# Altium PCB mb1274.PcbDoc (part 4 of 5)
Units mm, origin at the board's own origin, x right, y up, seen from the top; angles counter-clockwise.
Board outline 70 x 105 mm, 4 copper layers (Top Layer, Mid-Layer 1, Mid-Layer 2, Bottom Layer), stack 1.58 mm thick; 329 components, 271 nets, 1213 pads, 779 vias.
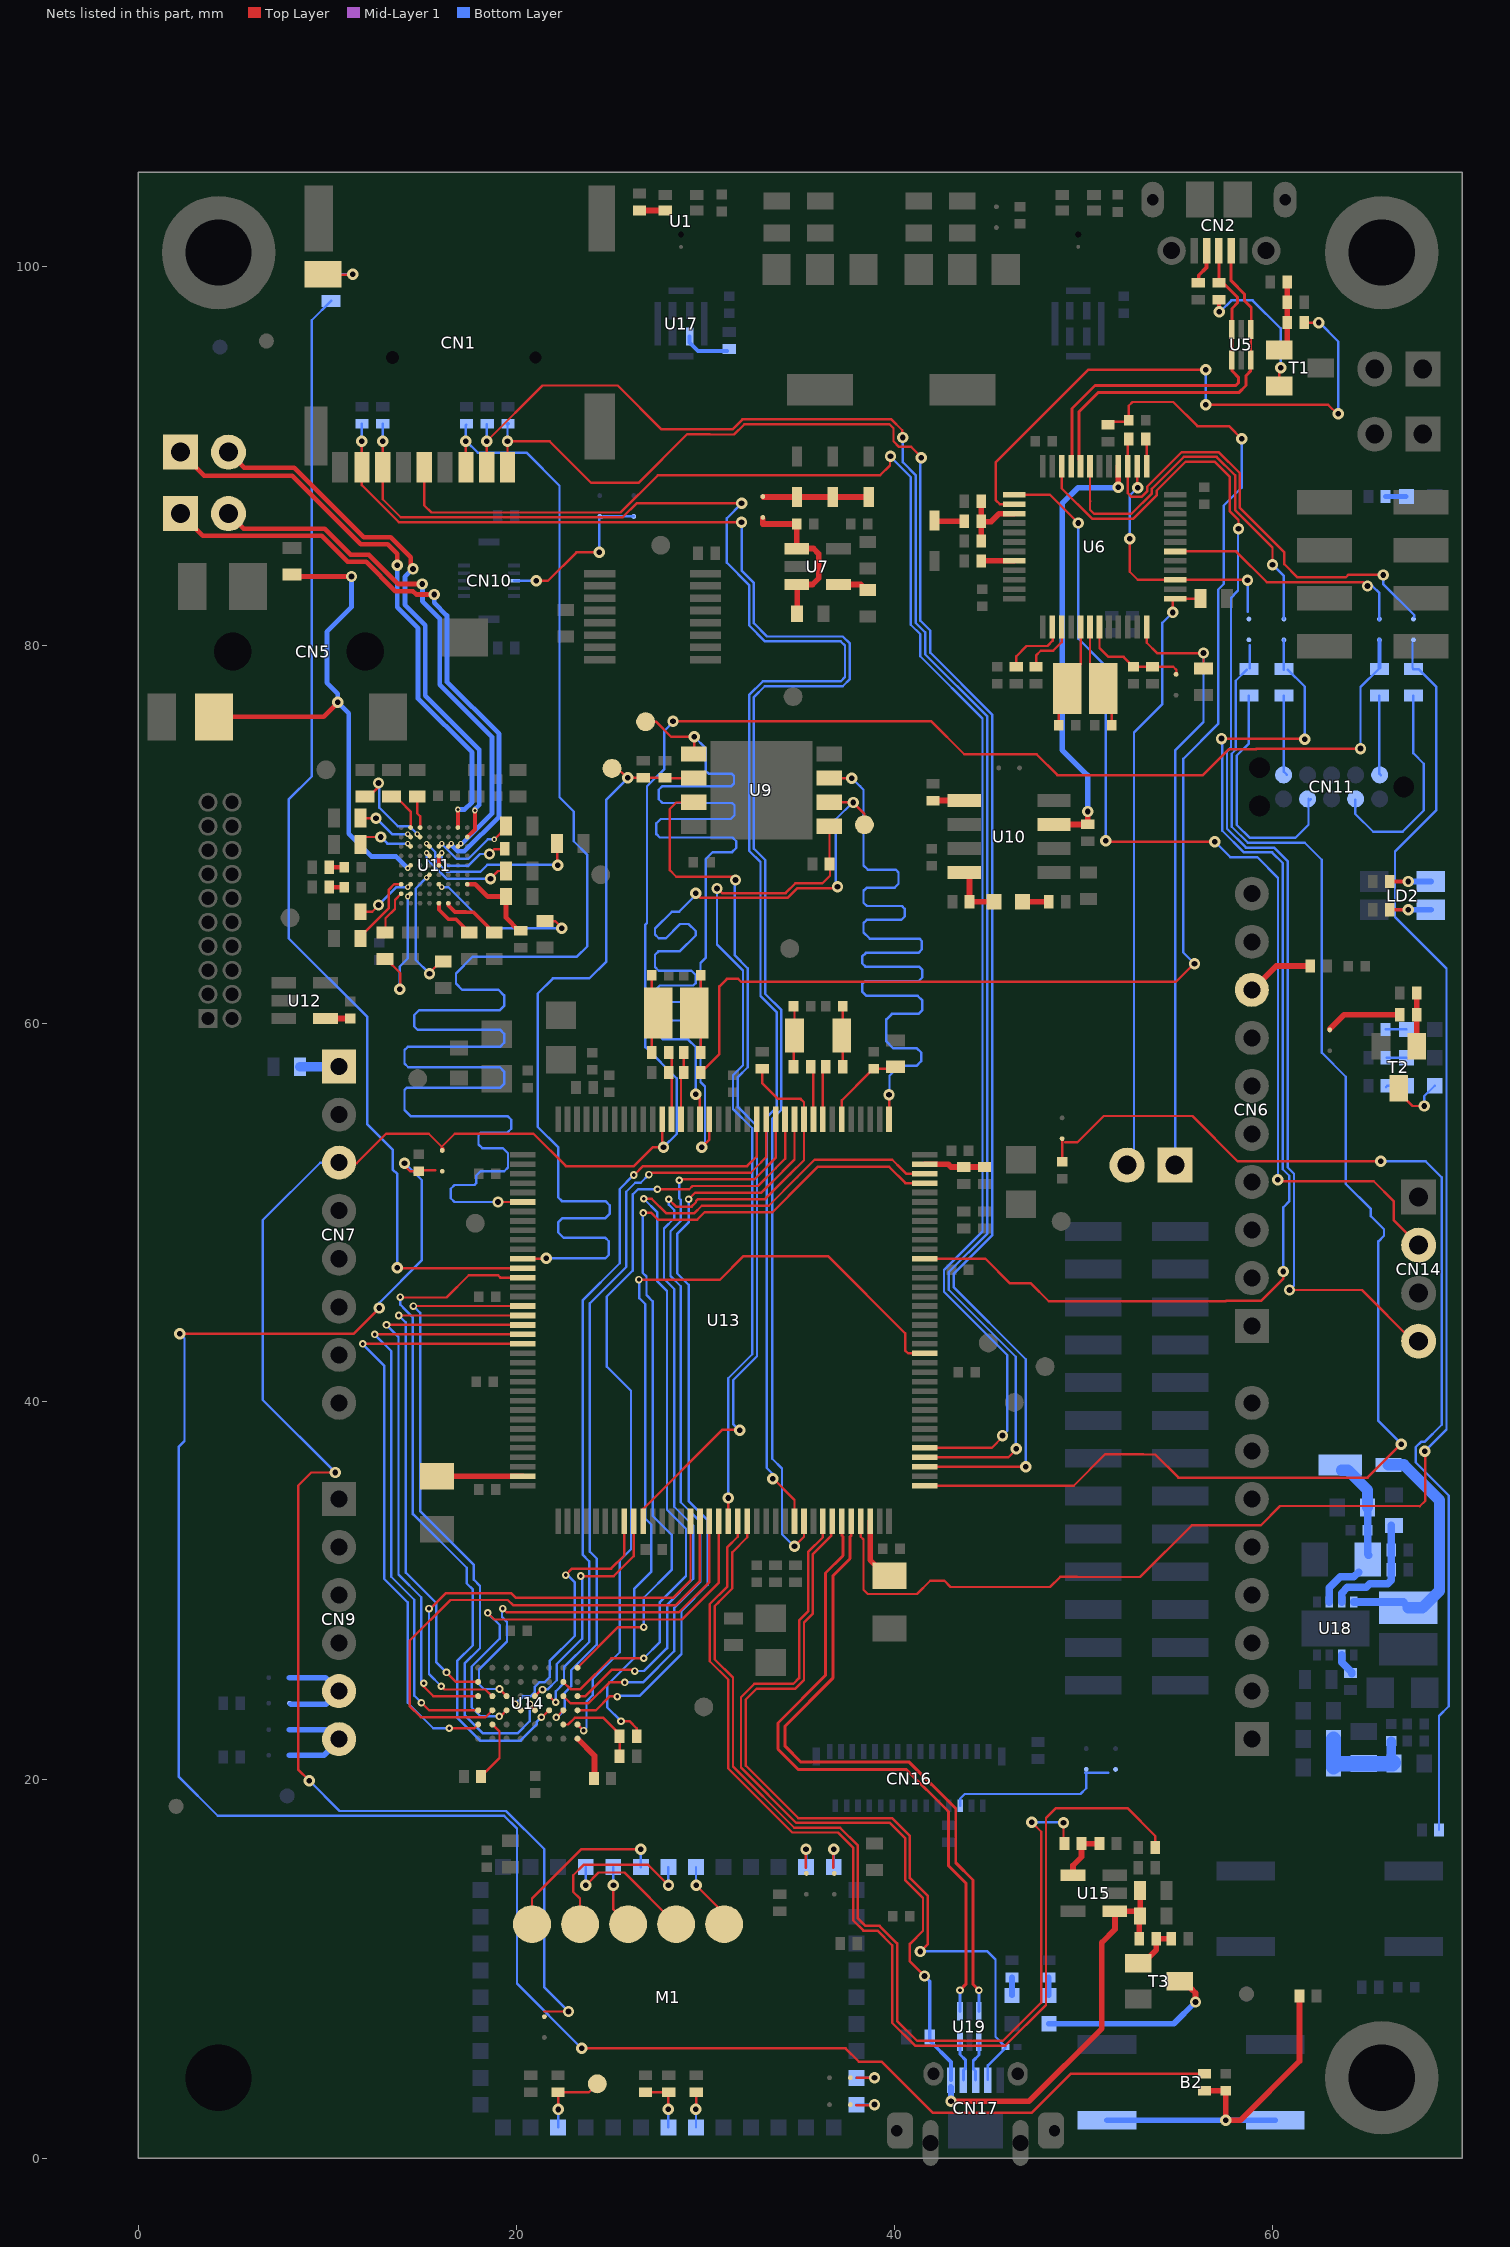
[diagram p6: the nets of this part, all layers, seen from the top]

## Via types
v1: diameter 0.6, hole 0.3, Top Layer to Bottom Layer, tented both sides, 574 vias
v2: diameter 0.4, hole 0.2, Top Layer to Bottom Layer, tented both sides, 125 vias
v3: diameter 0.8, hole 0.4, Top Layer to Bottom Layer, tented both sides, 49 vias
v4: diameter 0.3, hole 0.15, Top Layer to Bottom Layer, tented both sides, 31 vias

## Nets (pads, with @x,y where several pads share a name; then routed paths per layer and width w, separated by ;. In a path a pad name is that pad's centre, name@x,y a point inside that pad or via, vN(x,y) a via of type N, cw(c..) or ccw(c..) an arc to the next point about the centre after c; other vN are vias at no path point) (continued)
NetB2_1: B2.1 B2.2 C78.2 R72.1 R73.2 | length 20.2
  Top Layer w0.3: R73.2@56.375,3.55 C78.2@57.5,3.55 v1(57.5,2) 58.275,2 61.4,5.125 R72.1@61.4,8.575
  Bottom Layer w0.3: B2.1@51.225,2 v1(57.5,2) B2.2@60.125,2
NetC11_2: C11.2 C17.2 SB2.2 U7.1 U7.3 | length 8.7
  Top Layer w0.3: SB2.2@33.025,86.675 33.025,86.4 C11.2@34.825,86.4 U7.1@34.825,85.1 ; C17.2@34.825,81.65 34.85,81.675 U7.3@34.85,83.2 ; U7.3@34.825,83.2 U7.3@34.85,83.2 ; U7.1@34.875,85.1 35.7,85.1 35.975,84.825 35.975,83.525 35.65,83.2 U7.3@34.85,83.2
NetC14_2: C14.2 U7.4 | length 1.5
  Top Layer w0.3: U7.4@37.025,83.2 38.2,83.2 C14.2@38.425,82.975
NetC22_2: C22.2 U11.F1 | length 1.7
  Top Layer w0.127: C22.2@14.75,72 14.75,71.1 14.903,70.947 U11.F1@14.903,70.328
NetC29_1: C29.1 R32.2 | length 0.8
  Top Layer w0.25: R32.2@10.125,68.25 C29.1@10.9,68.25
NetC31_1: C31.1 R35.2 | length 0.8
  Top Layer w0.25: R35.2@10.1,67.2 C31.1@10.9,67.2
NetC32_2: C32.2 R39.1 U11.A7 | length 4.5
  Top Layer w0.25: U11.A7@17.4,67.35 17.825,67.35 18.475,66.7 C32.2@19.45,66.7 19.45,65.575 20.125,64.9 R39.1@20.225,64.9
NetC33_1: C33.1 U11.G7 | length 3.3
  Top Layer w0.127: C33.1@11.75,65.9 12.375,65.9 12.701,66.226 v1(12.701,66.253) ; v4(14.25,67.2) U11.G7@14.4,67.35
  Bottom Layer w0.127: v1(12.701,66.253) 13.647,67.2 v4(14.25,67.2)
NetC34_2: C34.2 U11.D7 | length 8.6
  Top Layer w0.127: U11.D7@15.9,67.35 v4(16.05,67.2) v4@16.075,67.2 ; C34.2@21.4,65.4 C34.2@21.45,65.35 ; C34.2@21.5,65.4 22.05,65.4 v1@22.4,65.05
  Bottom Layer w0.127: v4@16.075,67.2 16.39,67.2 18.565,65.025 v1(22.4,65.025)
NetC36_1: C36.1 U11.H8 | length 2.4
  Top Layer w0.127: C36.1@13.075,64.8 13.075,65.55 13.575,66.05 13.575,66.525 U11.H8@13.9,66.85
NetC36_2: C36.2 U11.G8 | length 7.2
  Top Layer w0.127: C36.2@13.05,63.4 13.1,63.4 13.85,62.65 v1@13.85,61.8 ; v4(14.25,66.7) U11.G8@14.4,66.85
  Bottom Layer w0.127: v1@13.825,61.85 13.825,63 14.25,63.425 v4(14.25,66.7) ; v1@13.85,61.8 v1@13.85,61.85
  other v1: 13.825,61.8
NetC38_2: C38.2 U11.D9 | length 2.4
  Top Layer w0.2: U11.D9@15.9,66.35 15.9,66 16.4,65.5 16.8,65.5 C38.2@17.5,64.8
NetC39_2: C39.2 U11.C9 | length 3.1
  Top Layer w0.2: U11.C9@16.4,66.35 16.4,66.225 16.748,65.877 17.3,65.877 ; 17.3,65.875 17.725,65.875 C39.2@18.8,64.8
NetC40_1: C40.1 U11.H7 | length 3.8
  Top Layer w0.127: C40.1@11.825,64.675 13.25,66.1 13.25,67.075 13.525,67.35 U11.H7@13.9,67.35
NetC41_2: C41.2 U11.E6 | length 6.8
  Top Layer w0.127: v4(15.25,67.7) U11.E6@15.4,67.85 ; v1(15.401,62.628) 15.401,62.676 16,63.275 C41.2@16.125,63.275
  Bottom Layer w0.127: v4(15.25,67.7) 14.675,67.125 14.675,63.354 v1(15.401,62.628)
NetC43_1: C43.1 R44.2 X2.2 | length 4.1
  Top Layer w0.127: X2.2@27,60.7 27.15,60.85 C43.1@27.15,62.55 ; R44.2@27.15,58.45 27.15,60.175 X2.2@27.5,60.525
NetC44_1: C44.1 R45.2 X2.1 | length 3.9
  Top Layer w0.127: X2.1@29.7,60.2 29.75,60.15 R45.2@29.75,58.45 ; X2.1@29.75,60.375 C44.1@29.75,62.55
NetC45_2: C45.2 U12.4 | length 1.4
  Top Layer w0.3: U12.4@9.825,60.275 9.85,60.25 U12.4@9.9,60.25 C45.2@11.2,60.25
NetC46_1: C46.1 R47.2 X3.2 | length 3
  Top Layer w0.127: R47.2@34.65,57.7 34.65,59.075 X3.2@34.675,59.1 ; C46.1@34.675,60.9 34.7,60.875 X3.2@34.7,59.35
NetC47_1: C47.1 R48.2 X3.1 | length 3.2
  Top Layer w0.127: R48.2@37.25,57.7 X3.1@37.25,59.175 ; C47.1@37.25,60.9 37.25,59.25 X3.1@37.275,59.225
NetC50_2: C50.2 R43.1 U13.6 | length 4.4
  Top Layer w0.127: U13.6@37.2,54.925 37.2,55.925 C50.2@38.7,57.425 ; C50.2@38.9,57.6 39.95,57.6 R43.1@40.1,57.75
NetC57_2: C57.2 R73.1 SB7.2 | length 113.1
  Top Layer w0.127: v1(2.2,43.577) 2.202,43.575 11.375,43.575 v1(12.75,44.95) ; v1@14.075,52.625 v1(14.075,52.6) 14.075,52.475 14.375,52.175 C57.2@14.825,52.175 ; C57.2@14.85,52.225 15.7,52.225 ; v1(23.45,5.8) 37.4,5.8 38.1,5.1 39.3,5.1 42,2.4 47.25,2.4 49.3,4.45 R73.1@56.375,4.45
  Bottom Layer w0.127: v1(2.2,43.577) 2.446,43.331 2.446,37.921 2.15,37.625 2.15,20.15 4.204,18.096 19.345,18.096 20.025,17.416 20.025,9.225 v1(23.45,5.8) ; v1(12.75,44.95) 12.75,45.225 15,47.475 15,51.7 v1@14.088,52.613 ; v1@13.85,52.6 v1(14.075,52.6)
NetC58_2: C58.2 R106.1 SB6.2 | length 59.1
  Top Layer w0.127: C58.2@48.85,52.675 SB6.2@48.85,53.85 ; 49,53.7 49.65,53.7 51.05,55.1 55.741,55.1 58.14,52.701 v1(65.7,52.7)
  Bottom Layer w0.127: v1(65.7,52.7) 68.075,52.7 68.921,51.854 68.921,38.771 68.017,37.867 67.825,37.867 67.538,37.58 67.538,36.787 69.29,35.034 69.29,23.89 68.775,23.375 R106.1@68.775,17.35
NetC64_2: C64.2 U13.71 | length 4.6
  Top Layer w0.3: C64.2@15.775,36.05 U13.71@20.325,36.05
NetC69_2: C69.2 U13.106 | length 2.8
  Top Layer w0.3: U13.106@38.7,33.675 38.7,31.625 C69.2@39.225,31.1
NetC83_2: C83.2 C84.2 D5.2 L3.1 U18.6 | length 7.9
  Bottom Layer w0.4: U18.6@62.975,29.4 62.975,30.15 63.55,30.725 64.275,30.725 C84.2@64.525,30.975 ; L3.1@65,34.4 65,33 65,31.925 C84.2@65.05,31.875
  Bottom Layer w0.6: D5.2@63.625,36.375 63.95,36.375 65,35.325 L3.1@65,34.4
NetC87_2: C87.2 C88.2 L6.2 L7.1 L8.2 | length 5.9
  Bottom Layer w0.5: C87.2@66.25,22.05 66.25,20.975 L7.1@66.325,20.9
  Bottom Layer w0.8: L8.2@63.2,20.675 L6.2@63.2,22.15 ; L8.2@63.225,20.7 63.375,20.85 C88.2@64.8,20.85 66.325,20.85 L7.1@66.375,20.9
NetCN1_10: CN1.10 R79.2 | length 2.5
  Top Layer w0.127: CN1.10@10.025,99.575 11.325,99.575 v1(11.35,99.6)
  Bottom Layer w0.127: R79.2@10.2,99.6 v1(11.35,99.6)
NetCN3_1: CN3.1 U11.B1 | length 30.3
  Top Layer w0.127: U11.B1@16.9,70.35 U11.B1@16.9,70.383
  Top Layer w0.2: U11.B1@16.9,70.383 v4(16.9,71.3)
  Top Layer w0.25: CN3.1@2.23,90.2 3.48,88.95 8.142,88.95 11.769,85.323 13.194,85.323 13.7,84.817 v1(13.7,84.225)
  Bottom Layer w0.25: v1(13.7,84.225) 13.7,81.992 14.798,80.894 14.798,77.169 17.648,74.319 17.648,71.698 17.25,71.3 v4(16.9,71.3)
NetCN3_2: CN3.2 U11.A2 | length 28.8
  Top Layer w0.2: U11.A2@17.4,69.85 17.8,70.25 v4(17.8,71.25)
  Top Layer w0.25: CN3.2@4.77,90.2 5.595,89.375 8.25,89.375 11.925,85.7 13.35,85.7 14.404,84.646 14.404,84.146 v1(14.525,84.025)
  Bottom Layer w0.25: v1(14.525,84.025) 14.1,83.6 14.1,82.125 15.175,81.05 15.175,77.325 18.025,74.475 18.025,71.542 17.8,71.317 v4(17.8,71.25)
NetCN4_1: CN4.1 U11.C3 | length 32.1
  Top Layer w0.2: U11.C3@16.4,69.35 v4(16.55,69.5)
  Top Layer w0.25: CN4.1@2.23,86.95 3.407,85.773 9.694,85.773 11.069,84.398 12.044,84.398 13.594,82.848 14.525,82.848 14.7,82.673 15.254,82.673 15.256,82.675 v1(15.65,82.675)
  Bottom Layer w0.25: v1(15.65,82.675) 15.65,82.233 16.325,81.558 16.325,78.05 19.077,75.298 19.077,70.925 17.25,69.098 16.883,69.098 16.55,69.431 v4(16.55,69.5)
NetCN4_2: CN4.2 U11.B3 | length 28
  Top Layer w0.2: U11.B3@16.9,69.35 v4(17.05,69.5)
  Top Layer w0.25: CN4.2@4.77,86.95 5.57,86.15 9.85,86.15 11.225,84.775 12.2,84.775 13.75,83.225 v1(15.025,83.225)
  Bottom Layer w0.25: v1(15.025,83.225) 15.025,82.325 15.948,81.402 15.948,77.894 18.7,75.142 18.7,71.081 17.119,69.5 v4(17.05,69.5)
NetCN5_3: CN5.3 R12.1 U11.G5 | length 28.6
  Top Layer w0.25: CN5.3@4,76.2 4,76.202 9.802,76.202 10.575,76.975 v1(10.55,76.975) ; R12.1@8.15,83.7 8.225,83.625 v1(11.275,83.625)
  Bottom Layer w0.25: v1(11.275,83.625) 11.275,82 9.975,80.7 9.975,78 10.55,77.425 v1(10.55,76.975) 11.125,76.4 11.125,70.025 12.325,68.825 13.625,68.825 v4(14.25,68.2)
NetCN6_8: CN6.8 R40.1 | length 3.6
  Top Layer w0.3: CN6.8@58.925,61.775 60.175,63.025 R40.1@61.975,63.025
NetCN7_1: CN7.1 R95.2 | length 2.1
  Bottom Layer w0.2: CN7.1@10.65,57.7 CN7.1@10.675,57.675
  Bottom Layer w0.5: R95.2@8.55,57.7 CN7.1@10.65,57.7
NetCN9_5: CN9.5 SB19.2 SB20.2 | length 5.7
  Bottom Layer w0.3: SB19.2@8,25.4 9.9,25.4 CN9.5@10.55,24.75 ; SB20.2@8.075,24 9.93,24 CN9.5@10.62,24.69
NetCN9_6: CN9.6 SB21.2 SB24.2 | length 5.8
  Bottom Layer w0.3: SB24.2@8,21.3 9.825,21.3 CN9.6@10.637,22.113 ; SB21.2@8,22.65 10.1,22.65 CN9.6@10.6,22.15
NetCN10_8: CN10.8 SB13.2 SB14.2 | length 8.7
  Top Layer w0.127: v1(21.05,83.4) 21.666,83.4 23.166,84.9 v1(24.375,84.9)
  Bottom Layer w0.127: CN10.8@19.875,83.4 v1(21.05,83.4) ; v1(24.375,84.9) 24.375,86.75 SB14.2@24.4,86.775 ; SB14.2@24.5,86.725 24.575,86.8 SB13.2@26.2,86.8
NetCN16_24: CN16.24 SB22.2 SB23.2 | length 9.3
  Bottom Layer w0.127: CN16.24@43.46,18.625 43.46,19.01 43.7,19.25 49.825,19.25 50.125,19.55 50.125,20.325 50.15,20.35 ; 50.075,20.375 51.3,20.375
NetD1_2: D1.2 D2.2 D3.2 SB2.1 | length 5.5
  Top Layer w0.3: SB2.1@33.05,87.825 33.055,87.83 D1.2@34.825,87.83 ; D1.2@34.925,87.8 34.955,87.83 D2.2@36.725,87.83 ; D2.2@36.75,87.825 38.62,87.825 D3.2@38.625,87.83
NetD4_2: D4.2 R10.2 | length 1.6
  Top Layer w0.3: D4.2@42.05,86.525 42.075,86.55 R10.2@43.675,86.55
NetD5_1: D5.1 L4.2 U18.8 | length 13.3
  Bottom Layer w0.4: U18.8@64.275,29.4 66.9,29.4 L4.2@67.175,29.125
  Bottom Layer w0.6: D5.1@66.1,36.65 D5.1@66.115,36.65 66.928,36.65 68.8,34.778 68.8,30 67.9,29.1 L4.2@67.15,29.1
NetL2_2: L2.2 R98.2 R99.1 U18.7 | length 6.3
  Bottom Layer w0.4: U18.7@63.625,29.4 63.625,29.875 63.925,30.175 64.925,30.175 65.125,30.375 66.075,30.375 66.25,30.55 R99.1@66.25,31.15 ; R99.1@66.25,31.1 R98.2@66.25,32.125 ; R98.2@66.25,32.15 L2.2@66.25,33.45
NetLD1_1: LD1.1 R37.1 | length 1.4
  Top Layer w0.3: LD1.1@46.75,66.425 R37.1@48.15,66.425 R37.1@48.175,66.425
NetLD1_2: LD1.2 R36.1 U10.8 | length 2.8
  Top Layer w0.3: U10.8@43.85,67.875 43.95,67.775 R36.1@43.95,66.425 ; R36.1@43.95,66.4 43.975,66.425 LD1.2@45.25,66.425
NetLD2_2: LD2.2 R38.1 | length 2.2
  Top Layer w0.2: R38.1@66.175,66 v1(67.15,66)
  Bottom Layer w0.3: v1(67.15,66) LD2.2@68.35,66
NetLD2_3: LD2.3 R34.1 | length 2.2
  Top Layer w0.2: R34.1@66.175,67.5 v1(67.15,67.5)
  Bottom Layer w0.3: v1(67.15,67.5) LD2.3@68.35,67.5
NetLD3_1: LD3.1 R93.2 | length 1.1
  Bottom Layer w0.127: R93.2@65.95,59.675 LD3.1@67.05,59.675
NetLD4_1: LD4.1 R94.1 | length 1
  Bottom Layer w0.127: R94.1@66.025,58.175 LD4.1@67.05,58.175
NetLD5_1: LD5.1 R96.1 | length 1.1
  Bottom Layer w0.127: R96.1@65.975,56.625 66.05,56.7 LD5.1@67.05,56.7
NetLD5_2: LD5.2 T2.3 | length 3.2
  Top Layer w0.127: T2.3@66.65,56.575 66.65,56.35 67.375,55.625 v1(68,55.625)
  Bottom Layer w0.127: v1(68,55.625) 68,56.15 LD5.2@68.55,56.7
NetLD6_1: LD6.1 R97.2 | length 1.1
  Bottom Layer w0.25: R97.2@65.95,87.85 LD6.1@67.05,87.85
NetLD7_1: LD7.1 R107.1 | length 1
  Bottom Layer w0.3: LD7.1@48.15,8.6 R107.1@48.15,9.55
NetLD7_2: LD7.2 T3.3 | length 9.1
  Top Layer w0.3: T3.3@55.65,8.975 55.9,8.725 v1(55.9,8.25)
  Bottom Layer w0.3: LD7.2@48.15,7.1 54.75,7.1 v1(55.9,8.25)
NetLD8_1: LD8.1 R108.2 | length 0.9
  Bottom Layer w0.3: LD8.1@46.2,8.6 R108.2@46.2,9.55
NetM1_4: M1.4 TP20.1 | length 7.1
  Top Layer w0.127: v1(23.668,14.425) 24.343,15.1 25.705,15.1 TP20.1@28.44,12.365
  Bottom Layer w0.127: M1.4@23.661,15.38 23.661,14.432 v1(23.668,14.425)
NetM1_5: M1.5 TP19.1 | length 3.3
  Top Layer w0.127: v1(25.125,14.425) 25.125,13.14 TP19.1@25.9,12.365
  Bottom Layer w0.127: M1.5@25.118,15.38 25.118,14.432 v1(25.125,14.425)
NetM1_6: M1.6 TP17.1 | length 9.1
  Top Layer w0.127: TP17.1@20.82,12.365 20.82,13.72 23.435,16.335 v1(26.568,16.335)
  Bottom Layer w0.127: v1(26.568,16.335) 26.575,16.328 M1.6@26.575,15.38
NetM1_7: M1.7 TP18.1 | length 9.4
  Top Layer w0.127: TP18.1@23.36,12.365 23.36,13.715 23,14.075 23,14.95 23.55,15.5 26.964,15.5 v1(28.039,14.425)
  Bottom Layer w0.127: M1.7@28.032,15.38 28.032,14.432 v1(28.039,14.425)
NetM1_8: M1.8 TP21.1 | length 3.6
  Top Layer w0.127: v1(29.496,14.425) 30.98,12.941 TP21.1@30.98,12.365
  Bottom Layer w0.127: M1.8@29.489,15.38 29.489,14.432 v1(29.496,14.425)
NetM1_12: M1.12 SB8.2 | length 1.9
  Top Layer w0.127: 35.3,15.35 35.3,16.325 v1(35.31,16.335)
  Bottom Layer w0.127: v1(35.31,16.335) 35.317,16.328 M1.12@35.317,15.38
NetM1_13: M1.13 SB9.2 | length 1.9
  Top Layer w0.127: 36.75,15.35 36.75,16.318 v1(36.767,16.335)
  Bottom Layer w0.127: v1(36.767,16.335) 36.774,16.328 M1.13@36.774,15.38
NetM1_21: M1.21 SB11.2 | length 1.9
  Top Layer w0.127: 38,4.25 38.926,4.25 v1(38.929,4.247)
  Bottom Layer w0.127: M1.21@37.974,4.24 38.922,4.24 v1(38.929,4.247)
NetM1_22: M1.22 SB12.2 | length 1.9
  Top Layer w0.127: 37.975,2.8 38.902,2.8 v1(38.929,2.827)
  Bottom Layer w0.127: M1.22@37.974,2.82 38.922,2.82 v1(38.929,2.827)
NetM1_28: M1.28 R78.2 | length 1.9
  Top Layer w0.127: v1(29.482,2.575) 29.5,2.593 R78.2@29.5,3.475
  Bottom Layer w0.127: v1(29.482,2.575) 29.489,2.568 M1.28@29.489,1.62
NetM1_29: M1.29 R76.1 R77.2 | length 3
  Top Layer w0.127: R76.1@26.825,3.475 28,3.475 28.025,3.45 v1(28.025,2.575)
  Bottom Layer w0.127: v1(28.025,2.575) 28.032,2.568 M1.29@28.032,1.62
NetM1_33: M1.33 R75.1 TP22.1 | length 4.1
  Top Layer w0.127: v1(22.204,2.571) 22.2,2.575 R75.1@22.2,3.475 23.825,3.475 TP22.1@24.275,3.925
  Bottom Layer w0.127: M1.33@22.204,1.62 v1(22.204,2.571)
NetR1_2: R1.2 U1.2 | length 1.4
  Top Layer w0.3: R1.2@26.5,102.975 27.825,102.975 U1.2@27.875,102.925
NetR2_2: R2.2 R5.2 R6.1 T1.1 | length 3.5
  Top Layer w0.3: T1.1@60.425,95.7 60.75,96.025 R6.1@60.75,97.05 ; R6.1@60.75,97.1 R5.2@60.75,98.125 ; R5.2@60.75,98.2 R2.2@60.75,99.2
NetR4_2: R4.2 T1.2 | length 7.8
  Top Layer w0.127: T1.2@60.325,93.7 60.325,94.675 60.383,94.675 v1(60.403,94.655)
  Top Layer w0.2: R4.2@57.15,98.25 57.15,97.633 v1(57.153,97.63)
  Bottom Layer w0.127: v1@57.225,97.65 57.8,98.225 58.925,98.225 60.403,96.747 v1(60.403,94.655)
NetR14_2: R14.2 U6.44 | length 1.8
  Top Layer w0.3: R14.2@44.55,84.425 R14.2@44.575,84.45 U6.44@46.325,84.45
NetR16_1: R16.1 U6.2 | length 3.5
  Top Layer w0.127: R16.1@46.425,78.85 46.425,79.4 46.975,79.95 48.075,79.95 48.35,80.225 U6.2@48.35,80.875
NetR17_1: R17.1 U6.3 | length 3
  Top Layer w0.127: R17.1@47.475,78.85 47.475,79.45 47.721,79.696 48.371,79.696 48.825,80.15 U6.3@48.825,80.9
NetR22_2: R22.2 U11.F2 | length 5.2
  Top Layer w0.127: R22.2@12.1,71.9 12.701,72.501 v1(12.701,72.704) ; v4(14.75,70) U11.F2@14.9,69.85
  Bottom Layer w0.127: v1(12.701,72.704) 12.75,72.654 12.75,71.4 13.725,70.425 14.325,70.425 v4(14.75,70)
NetR23_2: R23.2 U11.G1 | length 1.7
  Top Layer w0.127: R23.2@13.825,71.775 14.4,71.2 U11.G1@14.4,70.35
NetR24_2: R24.2 U10.5 | length 1.7
  Top Layer w0.3: R24.2@42.025,71.775 42.03,71.78 U10.5@43.675,71.78
NetR25_1: R25.1 U11.G2 | length 3.1
  Top Layer w0.127: R25.1@11.75,70.85 v1(12.575,70.85) ; v4@14.225,70.025 v4(14.25,70) U11.G2@14.4,69.85
  Bottom Layer w0.127: v1(12.575,70.85) 13.425,70 v4(14.25,70)
NetR26_1: R26.1 U11.D3 | length 4.7
  Top Layer w0.127: U11.D3@15.9,69.35 v4(16.05,69.5) ; v4(18.825,69.725) 19.45,70.35 R26.1@19.45,70.425
  Bottom Layer w0.127: v4(16.05,69.5) 16.05,69.485 16.835,68.7 17.459,68.7 18.484,69.725 v4(18.825,69.725)
NetR28_2: R28.2 U11.E3 | length 9.3
  Top Layer w0.127: v4(15.25,69.5) U11.E3@15.4,69.35 ; R28.2@22.15,69.5 22.15,68.375 v1(22.175,68.35)
  Bottom Layer w0.127: v4(15.25,69.5) 15.71,69.04 15.71,68.615 16.315,68.01 18.091,68.01 18.457,68.375 v1@22.175,68.375
NetR29_2: R29.2 U11.G3 | length 3
  Top Layer w0.127: R29.2@11.7,69.675 11.875,69.85 v1(12.825,69.85) ; v4(14.25,69.5) U11.G3@14.4,69.35
  Bottom Layer w0.127: v1@12.8,69.875 v1(12.825,69.85) 13.175,69.5 v4(14.25,69.5)
NetR30_2: R30.2 U11.D4 U11.D5 | length 4.9
  Top Layer w0.127: U11.D4@15.9,68.85 v4(16.05,69) ; v1(18.575,68.95) 18.825,69.2 R30.2@19.35,69.2
  Top Layer w0.2: U11.D5@15.9,68.35 U11.D4@15.9,68.85
  Bottom Layer w0.127: v4(16.05,69) 16.05,68.65 16.375,68.325 17.443,68.325 18.068,68.95 v1(18.575,68.95)
NetR33_2: R33.2 U11.E4 | length 5.3
  Top Layer w0.127: v4(15.25,69) U11.E4@15.4,68.85 ; v1(18.625,67.65) 19.025,68.05 R33.2@19.425,68.05
  Bottom Layer w0.127: v4(15.25,69) 15.25,68.7 16.3,67.65 v1(18.625,67.65)
NetR41_2: R41.2 R42.2 T2.1 | length 2.8
  Top Layer w0.3: T2.1@67.6,58.775 R42.2@67.6,60.45 R41.2@67.6,61.6
NetR42_1: R42.1 SB5.2 | length 4
  Top Layer w0.3: SB5.2@63,59.7 63.75,60.45 R42.1@66.7,60.45
NetR59_2: R59.2 R60.1 U14.B5 | length 4.5
  Top Layer w0.127: U14.B5@22.475,22.925 22.729,22.925 23.08,23.276 23.37,23.276 24.6,23.275 R59.2@25.425,22.45 ; R59.2@25.425,22.275 25.45,22.25 R60.1@25.45,21.25
NetR61_2: R61.2 U14.G5 | length 3.3
  Top Layer w0.127: R61.2@18.125,20.175 19.1,21.15 19.1,22.55 U14.G5@18.725,22.925
NetR62_1: R62.1 U14.A6 | length 2.6
  Top Layer w0.3: U14.A6@23.225,22.175 24.125,21.275 R62.1@24.125,19.975
NetR63_2: R63.2 R64.1 U15.4 | length 2.9
  Top Layer w0.3: U15.4@49.425,14.95 49.425,15.475 49.875,15.925 R63.2@49.875,16.625 R64.1@50.825,16.625 ; U15.4@49.425,15 U15.4@49.475,14.95
NetR69_2: R69.2 R70.2 T3.1 | length 2.6
  Top Layer w0.3: T3.1@52.9,10.3 53.125,10.3 53.825,11 R69.2@53.825,11.6 ; R69.2@53.85,11.6 R70.2@54.625,11.6
NetR80_2: R80.2 U17.2 | length 2.5
  Bottom Layer w0.2: U17.2@29.15,96.325 29.15,96 29.6,95.55 R80.2@31.125,95.55
NetR100_2: R100.2 U18.2 | length 1.2
  Bottom Layer w0.4: U18.2@63.625,26.6 63.625,26.225 64.175,25.675 R100.2@64.175,25.6
NRST: CN7.3 R90.2 SB7.1 SB10.1 SB16.2 U13.25 | length 152.3
  Top Layer w0.127: v1(9.05,19.95) 8.45,20.55 8.45,35.55 9.15,36.25 v1(10.425,36.25) ; CN7.3@10.625,52.6 11.543,52.6 13.106,54.163 15.362,54.163 16.05,53.475 ; SB7.1@16.05,53.3 16.05,53.475 ; SB7.1@16.125,53.275 16.125,53.4 16.05,53.475 ; 21.475,7.75 v1(22.75,7.75) ; v1@27.7,53.452 U13.25@27.7,54.9 ; v1(27.776,53.452) 27.774,53.45 27.209,53.45 26.209,52.45 22.615,52.45 20.902,54.163 16.738,54.163 16.05,53.475 ; v1(28.276,75.979) 41.921,75.979 43.675,74.225 47.5,74.225 48.6,73.125 56.3,73.125 57.675,74.5 59.125,74.5 ; 59.125,74.51 64.609,74.51 v1(64.625,74.525)
  Bottom Layer w0.127: v1(9.05,19.95) 10.65,18.35 19.45,18.35 21.475,16.325 21.475,9.025 v1(22.75,7.75) ; v1(10.425,36.25) 6.587,40.088 6.587,49.591 9.626,52.63 CN7.3@10.62,52.63 ; v1(27.776,53.452) 28.475,54.151 28.475,57.084 26.816,58.743 26.816,65.216 26.9,65.3 26.9,72.532 27.817,73.448 27.817,75.467 28.276,75.926 v1(28.276,75.979) ; v1(64.625,74.525) 64.625,77.775 R90.2@65.6,78.75
  Bottom Layer w0.2: R90.2@65.625,78.8 SB16.2@65.625,80.275
OSC32_IN: R48.1 U13.8 | length 2.6
  Top Layer w0.127: U13.8@36.2,54.925 36.2,57.45 R48.1@36.25,57.5
OSC32_OUT: R47.1 U13.9 | length 2.9
  Top Layer w0.127: R47.1@35.5,57.7 35.7,57.5 U13.9@35.7,54.925
OSC_IN: C20.1 U6.5 X1.2 | length 4.6
  Top Layer w0.127: X1.2@48.65,77.675 48.675,77.65 C20.1@48.675,75.75 ; X1.2@49.325,78.475 49.825,78.975 U6.5@49.825,80.95
OSC_OUT: C21.1 U6.6 X1.1 | length 4.4
  Top Layer w0.127: U6.6@50.325,80.95 50.325,78.75 X1.1@50.45,78.625 ; C21.1@51.475,75.75 51.475,77.725 X1.1@51.525,77.775
PDR_ON: R52.1 R53.2 U13.143 | length 3.2
  Top Layer w0.3: U13.143@41.575,52.55 42.825,52.55 42.975,52.4 R52.1@43.65,52.4 R53.2@44.75,52.4
PH0-OSC_IN: R45.1 R50.1 U13.23 | length 3.4
  Top Layer w0.127: U13.23@28.7,54.925 28.7,57.25 R50.1@28.75,57.3 ; R50.1@28.85,57.4 R45.1@28.85,58.45
PH1-OSC_OUT: R44.1 R49.1 U13.24 | length 3.6
  Top Layer w0.127: R44.1@28,58.425 28.2,58.225 U13.24@28.2,54.925
PSRAM_A0: R46.1 U13.10 U14.A3 | length 46
  Top Layer w0.127: U14.A3@23.225,24.425 23.65,24.425 25.05,25.825 26.251,25.825 26.275,25.825 26.275,25.774 v2(26.251,25.751) ; v2(28.05,50.7) 28.44,50.31 29.262,50.31 29.49,50.538 29.49,50.6 29.594,50.703 33.147,50.703 34.466,52.022 34.466,52.027 35.2,52.76 35.2,53.475 U13.10@35.2,54.925 35.2,55.825 35.025,56 33.825,56 33,56.825 R46.1@33,57.6
  Bottom Layer w0.127: v2(26.251,25.751) 26.575,25.751 26.75,25.75 27.962,26.962 27.962,29.246 29.343,30.627 29.343,33.429 28.338,34.434 28.338,45.953 27.797,46.494 27.797,49.147 28.338,49.688 28.338,50.125 28.05,50.413 v2(28.05,50.7)
PSRAM_A1: U13.11 U14.A4 | length 40.9
  Top Layer w0.127: U14.A4@23.225,23.675 24.2,23.675 24.95,24.425 25.302,24.425 v2(25.326,24.401) ; v2(29.1,50.7) 29.45,51.05 32.955,51.05 34.085,52.18 34.085,52.184 34.7,52.799 U13.11@34.7,54.925
  Bottom Layer w0.127: v2(25.326,24.401) 25.375,24.449 26.527,24.449 28.725,26.647 28.725,26.975 ; 28.724,26.975 28.724,28.93 30.105,30.311 30.105,33.745 29.1,34.75 29.1,46.172 28.491,46.781 28.491,48.86 29.1,49.469 v2(29.1,50.7)
PSRAM_A2: U13.12 U14.A5 | length 41.9
  Top Layer w0.127: U14.A5@23.225,22.925 v2(23.55,22.6) ; v2(27.45,51.225) 29.134,51.225 29.306,51.397 32.763,51.397 33.704,52.338 33.704,52.342 34.2,52.838 34.2,53.125 U13.12@34.2,54.925
  Bottom Layer w0.127: v2(23.55,22.6) 23.701,22.751 23.701,24.143 24.036,24.478 24.036,25.326 25.456,26.746 25.456,31.595 26.052,32.191 26.052,40.573 24.775,41.85 24.775,45.55 26.15,46.925 26.15,50.95 26.425,51.225 v2(27.45,51.225)
PSRAM_A3: U13.13 U14.B3 | length 41.2
  Top Layer w0.127: U14.B3@22.475,24.425 22.856,24.044 23.808,24.044 24.914,25.15 v2(25.725,25.15) ; v2(28.6,51.7) 28.644,51.744 32.572,51.744 33.323,52.496 33.323,52.5 33.7,52.877 33.7,53.7 U13.13@33.7,54.925
  Bottom Layer w0.127: v2(25.725,25.15) 26.689,25.15 28.343,26.804 28.343,29.088 29.724,30.469 29.724,33.635 28.685,34.674 28.685,46.096 28.144,46.637 28.144,49.003 28.685,49.544 28.685,50.665 28.6,50.75 v2(28.6,51.7)
PSRAM_A4: U13.14 U14.B4 | length 40.4
  Top Layer w0.127: v2(22.1,23.3) U14.B4@22.475,23.675 ; v2(27,52) 27.1,52.1 32.389,52.1 32.942,52.654 32.942,52.658 33.2,52.915 U13.14@33.2,54.925
  Bottom Layer w0.127: v2(22.1,23.3) 22.15,23.3 22.558,23.708 22.558,24.617 22.893,24.952 22.893,25.799 24.233,27.14 24.233,28.125 24.244,28.136 24.244,31.695 23.882,32.057 23.882,45.196 25.803,47.117 25.803,51.094 26.281,51.572 26.572,51.572 v2(27,52)
PSRAM_A5: U13.15 U14.C3 | length 39.3
  Top Layer w0.127: U14.C3@21.725,24.425 22.049,24.101 v2(22.076,24.101) ; v2(26.201,51.977) 26.227,51.977 26.697,52.447 32.197,52.447 32.7,52.95 32.7,54 U13.15@32.7,54.925
  Bottom Layer w0.127: v2(22.076,24.101) v2(22.076,24.101) 22.076,24.673 22.512,25.109 22.512,25.957 23.852,27.298 23.852,31.403 23.85,31.405 23.85,31.55 23.494,31.906 23.494,45.347 25.456,47.309 25.456,51.237 26.138,51.919 26.197,51.919 26.228,51.95 v2(26.201,51.977)
PSRAM_A6: U13.50 U14.C4 | length 37.2
  Top Layer w0.127: v2@13.875,45.5 16.3,45.5 17.475,46.675 19.025,46.675 19.15,46.55 U13.50@20.325,46.55 ; v2(21.319,23.306) 21.356,23.306 U14.C4@21.725,23.675
  Bottom Layer w0.127: v2@13.85,45.5 13.85,45.125 14.1,44.875 14.524,44.451 14.524,34.051 17.367,31.208 17.367,30.383 17.691,30.059 17.691,27.116 16.875,26.3 16.875,23.275 18.075,22.075 20.214,22.075 ; 20.225,22.075 20.214,22.075 ; v2@21.3,23.3 21.081,23.081 21.081,22.942 20.214,22.075
  other v2: 13.85,45.525
PSRAM_A7: U13.53 U14.D4 | length 34.6
  Top Layer w0.127: v2(14.55,45.05) U13.53@20.325,45.05 ; v2(20.707,24.004) 20.707,23.943 U14.D4@20.975,23.675
  Bottom Layer w0.127: v2(14.55,45.05) 14.905,44.695 14.905,34.209 17.748,31.366 17.748,30.577 18.072,30.253 18.072,26.959 17.256,26.142 17.256,23.433 18.233,22.456 20.056,22.456 20.7,23.1 v2@20.7,24
PSRAM_A8: U13.54 U14.H2 | length 28.4
  Top Layer w0.127: v2(13.775,44.55) U13.54@20.325,44.55 ; v2(16.3,25.675) 16.8,25.175 U14.H2@17.975,25.175
  Bottom Layer w0.127: v2(13.775,44.55) 14.143,44.182 14.143,30.957 15.766,29.334 15.766,26.209 v2(16.3,25.675)
PSRAM_A9: U13.55 U14.H3 | length 30.2
  Top Layer w0.127: v2(13.126,44.052) 13.124,44.05 v2(13.126,44.052) U13.55@20.325,44.05 ; v2(15.1,25.1) 15.1,24.925 15.6,24.425 U14.H3@17.975,24.425
  Bottom Layer w0.127: v2@13.124,44.051 v2(13.126,44.052) ; v2@13.125,44.05 13.762,43.413 13.762,30.847 14.96,29.649 14.96,25.24 v2(15.1,25.1)
PSRAM_A10: U13.56 U14.H4 | length 31.4
  Top Layer w0.127: v2@12.55,43.55 16.7,43.55 19.2,43.55 U13.56@20.325,43.55 ; v2(14.975,24.075) 15.375,23.675 U14.H4@17.975,23.675
  Bottom Layer w0.127: v2@12.5,43.55 13.381,42.669 13.381,30.738 14.597,29.522 14.597,24.453 v2(14.975,24.075)
  other v2: 12.501,43.552
PSRAM_A11: U13.57 U14.H5 | length 32.8
  Top Layer w0.127: v2(11.875,43.05) 20.275,43.05 U13.57@20.3,43.075 ; v2(16.45,22.725) 17.775,22.725 U14.H5@17.975,22.925
  Bottom Layer w0.127: v2@11.85,43.05 11.862,43.038 13,41.9 13,30.628 14.25,29.378 14.25,24.075 15.6,22.725 v2(16.45,22.725)
PSRAM_A12: U13.87 U14.G3 | length 25.1
  Top Layer w0.127: v2(15.375,29.05) 15.449,29.05 16.255,29.856 19.733,29.856 19.971,29.618 28.277,29.618 29.2,30.541 U13.87@29.2,33.675 ; v2(16.025,24.95) 16.2,24.776 18.35,24.776 18.7,24.425 U14.G3@18.725,24.425
  Bottom Layer w0.127: v2(15.375,29.05) 15.376,25.599 v2(16.025,24.95)
PSRAM_A13: U13.88 U14.G4 | length 28.3
  Top Layer w0.127: U14.G4@18.725,23.675 18.356,23.306 14.944,23.306 14.35,23.9 14.35,27.35 16.509,29.509 19.541,29.509 19.813,29.237 28.434,29.237 29.7,30.503 U13.88@29.7,33.675
PSRAM_A14: U13.89 U14.F3 | length 21.3
  Top Layer w0.127: v2(19.1,24.8) U14.F3@19.475,24.425 ; v2(19.276,29.051) 19.471,28.856 28.592,28.856 30.2,30.464 30.2,31.125 U13.89@30.2,33.675
  Bottom Layer w0.127: v2(19.1,24.8) 18.268,24.8 18.018,25.05 18.018,25.827 19.496,27.305 19.496,28.342 19.232,28.607 19.232,29.007 v2(19.276,29.051)
PSRAM_A15: U13.90 U14.F4 | length 24.5
  Top Layer w0.127: v2(18.475,28.825) 18.825,28.475 28.75,28.475 30.7,30.425 U13.90@30.7,33.675 ; v2(19.088,23.349) 19.149,23.349 U14.F4@19.475,23.675
  Mid-Layer 1 w0.127: v2(19.088,23.349) v2@19.114,23.375
  Bottom Layer w0.127: v2(18.475,28.825) 19.115,28.185 19.115,27.463 17.637,25.984 17.637,23.825 18.113,23.349 v2(19.088,23.349)
PSRAM_A16: U13.80 U14.E4 | length 14.6
  Top Layer w0.127: v2(19.926,24.001) 19.926,23.974 U14.E4@20.225,23.675 ; v2(22.601,30.826) 22.942,31.167 25.003,31.167 25.7,31.864 U13.80@25.7,33.675
  Mid-Layer 1 w0.127: v2@19.924,24.001 v2(19.926,24.001)
  Bottom Layer w0.127: v2(19.926,24.001) 20.336,24.41 20.738,24.41 20.967,24.639 20.967,24.913 21.213,25.16 21.485,25.16 21.75,25.425 21.75,26.273 23.09,27.613 23.09,30.435 22.699,30.826 v2(22.601,30.826)
PSRAM_A17: U13.81 U14.D3 | length 12.7
  Top Layer w0.127: U14.D3@20.975,24.425 21.319,24.769 v2(21.375,24.769) ; v2(23.401,30.776) 23.416,30.761 25.136,30.761 26.2,31.825 26.2,32.925 U13.81@26.2,33.675
  Bottom Layer w0.127: v2(21.375,24.769) 21.384,24.779 21.642,24.779 22.131,25.267 22.131,26.115 23.471,27.455 23.471,30.679 23.388,30.762 23.374,30.776 v2(23.401,30.776)
PSRAM_NBL0: U13.141 U14.A1 | length 44.1
  Top Layer w0.127: U14.A1@23.225,25.925 25.375,28.075 v2(26.725,28.075) ; v2(26.7,49.975) 27.131,49.975 27.491,49.616 29.549,49.616 29.943,50.009 33.531,50.009 35.228,51.707 35.228,51.711 35.923,52.405 39.706,52.405 40.561,51.55 40.725,51.55 U13.141@41.575,51.55
  Bottom Layer w0.127: v2(26.7,49.975) 26.675,49.95 26.675,46.802 26.872,46.605 26.872,45.628 27.195,45.305 27.195,33.961 28.2,32.956 28.2,31.1 26.725,29.625 v2(26.725,28.075)
PSRAM_NBL1: U13.142 U14.B2 | length 47.9
  Top Layer w0.127: U14.B2@22.475,25.175 22.856,24.794 23.383,24.794 25.014,26.425 v2(26.725,26.425) ; v2(26.725,50.725) 27.147,50.725 27.909,49.963 29.405,49.963 29.799,50.356 33.339,50.356 34.847,51.865 34.847,51.869 35.765,52.786 39.864,52.786 40.35,52.3 40.6,52.05 U13.142@41.575,52.05
  Bottom Layer w0.127: v2(26.725,26.425) 27.581,27.281 27.581,29.403 28.962,30.784 28.962,33.272 27.957,34.277 27.957,45.843 27.45,46.35 27.45,50 v2(26.725,50.725)
PSRAM_NE1: R59.1 U13.123 | length 44.6
  Top Layer w0.127: v2(25.525,23.1) 25.975,23.1 26.35,22.725 R59.1@26.35,22.3 ; v2(26.475,46.45) 26.487,46.438 30.763,46.438 32.012,47.687 36.474,47.687 40.55,43.611 40.55,42.7 40.7,42.55 U13.123@41.575,42.55
  Bottom Layer w0.127: v2(25.525,23.1) 24.798,23.827 24.798,25.01 26.218,26.43 26.218,30.093 27.134,31.01 27.134,33.483 26.814,33.803 26.814,45.147 26.5,45.461 26.5,46.425 v2@26.525,46.45
PWR_ENN: R27.1 U6.28 U10.3 | length 23.7
  Top Layer w0.3: U10.3@48.425,70.51 50.21,70.51 R27.1@50.225,70.525 ; R27.1@50.2,70.525 v1(50.2,71.2) ; v1(51.825,88.35) U6.28@51.825,89.45
  Bottom Layer w0.3: v1(50.2,71.2) 50.2,73.1 48.85,74.45 48.85,87.475 49.7,88.325 v1@51.825,88.325
PWR_EXT: R9.2 R10.1 R11.1 U6.39 | length 4
  Top Layer w0.3: R11.1@44.575,85.5 44.575,86.5 R10.1@44.575,86.55 R9.2@44.575,87.6 ; R10.1@44.65,86.525 45.1,86.525 45.525,86.95 U6.39@46.325,86.95
QSPI_BK1_IO0: TP3.1 U9.5 U13.20 | length 45.8
  Top Layer w0.127: TP3.1@26.825,75.95 27.375,75.95 28.175,75.15 v1@29.375,75.15 ; U9.5@29.4,74.23 v1(29.4,75.15) ; v1(29.8,53.45) 30.2,53.85 U13.20@30.2,54.925
  Bottom Layer w0.127: v1(29.4,75.15) 30,74.55 30,73.35 30.15,73.2 31.375,73.2 31.5,73.075 31.5,72.675 31.35,72.525 27.7,72.525 27.525,72.35 27.525,71.85 27.725,71.65 31.4,71.65 31.525,71.525 31.525,71 31.325,70.8 27.625,70.8 27.4,70.575 27.4,70 27.575,69.825 31.425,69.825 31.621,69.629 31.621,69.271 31.4,69.05 30.375,69.05 30,68.675 30,63.45 29.729,63.179 29.729,56.9 29.966,56.664 29.966,53.616 v1(29.8,53.45)
QSPI_BK1_IO1: TP6.1 U9.2 U13.21 | length 42
  Top Layer w0.127: v1(29.475,56.25) 29.7,56.025 U13.21@29.7,54.925 ; v1(29.475,66.875) 29.719,66.631 34.332,66.631 34.85,67.15 36.925,67.15 v1@36.975,67.2 ; U9.2@36.525,71.69 37.8,71.69 37.815,71.69 v1(37.8,71.675) 38.4,71.075 TP6.1@38.4,70.5
  Bottom Layer w0.127: v1(29.475,56.25) 29.475,58.75 29.075,59.15 27.75,59.15 27.6,59.3 27.6,59.975 27.775,60.15 29.3,60.15 29.475,60.325 29.475,60.9 29.25,61.125 27.525,61.125 27.325,61.325 27.325,61.75 27.575,62 29.35,62 29.475,62.125 29.475,62.55 29.25,62.775 27.525,62.775 27.324,62.976 27.324,63.624 27.5,63.8 28.625,63.8 29.475,64.65 29.475,64.875 29.1,65.25 28.65,65.25 27.9,64.5 27.525,64.5 27.325,64.7 27.325,65.007 28.218,65.9 28.6,65.9 29.475,66.775 v1(29.475,66.875) ; v1(36.975,67.225) 36.885,67.315 36.885,70.784 37.788,71.687 v1@37.8,71.7
QSPI_BK1_IO2: U9.3 U13.1 | length 45.6
  Top Layer w0.127: U9.3@36.525,72.96 37.715,72.96 v1(37.725,72.95) ; U13.1@39.7,54.925 v1(39.7,56.225)
  Bottom Layer w0.127: v1@37.75,72.95 38.175,72.525 38.35,72.35 38.35,68.35 38.575,68.125 40.05,68.125 40.2,67.975 40.2,67.375 40,67.175 38.525,67.175 38.375,67.025 38.35,67.025 38.35,66.375 38.525,66.2 40.375,66.2 40.525,66.05 40.525,65.65 40.35,65.475 38.525,65.475 38.35,65.3 38.35,64.8 38.675,64.475 41.3,64.475 41.425,64.35 41.425,63.9 41.25,63.725 38.475,63.725 38.275,63.525 38.275,63.175 38.45,63 41.275,63 41.463,62.812 41.463,62.438 41.25,62.225 38.425,62.225 38.275,62.075 38.275,61.675 38.5,61.45 41.213,61.45 41.463,61.2 41.463,60.7 41.263,60.5 39.85,60.5 39.56,60.21 39.56,59.04 39.925,58.675 41.175,58.675 41.4,58.45 41.4,58 41.15,57.75 40.25,57.75 39.725,57.225 v1@39.725,56.225
QSPI_BK1_IO3: U9.7 U13.82 | length 46.6
  Top Layer w0.127: U13.82@26.7,33.675 26.7,34.325 30.875,38.5 v1@31.8,38.5 ; U9.7@29.425,71.675 29.375,71.675 28.45,71.675 28.1,71.325 28.1,68.1 28.45,67.75 31.405,67.75 v1(31.577,67.578)
  Bottom Layer w0.127: v1(31.577,67.578) 31.55,67.552 31.55,63.584 32.229,62.905 32.229,57.676 31.704,57.151 31.704,55.571 32.717,54.558 32.717,42.392 31.454,41.129 31.454,38.821 v1(31.8,38.475)
QSPI_BK1_NCS: R31.1 U9.1 U13.91 | length 44.2
  Top Layer w0.127: v1(30.6,67.125) 30.636,67.125 30.875,66.885 34.226,66.885 34.745,67.404 36.179,67.404 36.575,67.8 R31.1@36.575,68.375 ; U13.91@31.2,33.675 v1(31.2,34.9) ; R31.1@36.55,68.425 36.55,70.42 U9.1@36.55,70.425
  Bottom Layer w0.127: v1(30.6,67.125) 30.6,64.175 31.975,62.8 31.975,57.781 31.45,57.256 31.45,55.466 32.463,54.453 32.463,42.497 31.2,41.234 v1(31.2,34.9)
QSPI_CLK: R20.1 R21.1 TP4.1 U9.6 U13.48 | length 45.3
  Top Layer w0.127: U13.48@20.325,47.55 21.55,47.55 v1(21.575,47.575) ; TP4.1@25.05,73.475 25.35,73.475 25.862,72.963 v1@25.925,72.9 ; v1@25.925,72.975 R20.1@26.7,72.975 R21.1@27.85,72.975 ; R21.1@27.81,72.96 27.85,72.96 U9.6@29.375,72.96
  Bottom Layer w0.127: v1(21.575,47.575) 24.7,47.575 24.875,47.75 24.875,48.475 24.7,48.65 22.5,48.65 22.2,48.95 22.2,49.475 22.425,49.7 24.7,49.7 24.925,49.925 24.925,50.375 24.7,50.6 22.4,50.6 22.2,50.8 22.2,53.45 21.125,54.525 21.125,61.575 21.925,62.375 23.85,62.375 24.75,63.275 24.75,71.825 v1@25.875,72.95
  other v1: 25.875,72.975
SD_CLK: CN1.5 U13.113 | length 88.9
  Top Layer w0.127: CN1.5@15.125,89.4 15.125,87.383 15.5,87.008 25.508,87.008 27.475,88.975 39.225,88.975 39.75,89.5 v1@39.75,89.975 ; U13.113@41.575,37.55 45.125,37.55 45.738,38.162 45.775,38.2 v1(45.7,38.2)
  Bottom Layer w0.127: v1@39.825,89.925 39.825,89.907 40.85,88.882 40.85,81.075 41.35,80.575 41.35,79.407 44.642,76.115 44.642,48.991 42.604,46.953 42.604,45.806 45.948,42.461 45.948,40.551 45.946,40.549 45.946,38.446 v1@45.725,38.225 ; v1@45.7,38.175 v1(45.7,38.2) v1@45.7,38.225
  other v1: 39.775,89.975
SD_CMD: CN1.3 R83.1 U13.42 | length 93.6
  Top Layer w0.127: CN1.3@17.325,89.4 v1(17.325,90.775) v1@17.35,90.8 ; v1(19.025,50.55) U13.42@20.325,50.55
  Bottom Layer w0.127: R83.1@17.35,91.65 17.325,91.625 17.325,90.8 17.337,90.787 17.95,90.175 20.525,90.175 22.275,88.425 22.275,71.95 23.025,71.2 23.025,69.625 23.75,68.9 23.75,64.075 23.2,63.525 17.684,63.525 16.8,62.641 16.8,62.1 17.125,61.775 19.046,61.775 19.346,61.475 19.346,60.921 19.125,60.7 14.859,60.7 14.592,60.433 14.592,59.833 14.775,59.65 19.146,59.65 19.346,59.45 19.346,58.971 19.125,58.75 14.25,58.75 14.079,58.579 14.079,57.871 14.275,57.675 19.121,57.675 19.346,57.45 19.346,56.796 19.15,56.6 14.2,56.6 14.079,56.479 14.079,55.421 14.425,55.075 19.546,55.075 19.721,54.9 19.721,54.421 19.525,54.225 18.125,54.225 18,54.1 ; 17.99,54.1 17.99,53.6 18.19,53.4 19.275,53.4 19.55,53.125 19.55,52.375 19.35,52.175 18.1,52.175 17.875,51.95 17.875,51.55 17.775,51.45 16.725,51.45 16.525,51.25 16.525,50.75 16.725,50.55 v1(19.025,50.55)
SD_D0: CN1.7 R84.1 U13.98 | length 88.7
  Top Layer w0.127: v1(12.925,90.775) CN1.7@12.925,89.4 12.925,87.709 13.88,86.754 25.613,86.754 26.363,87.504 v1(31.902,87.504) ; v1(33.55,35.925) v1@33.562,35.913 ; v1@33.575,35.925 34.7,34.8 U13.98@34.7,33.675
  Bottom Layer w0.127: v1(12.925,90.775) R84.1@12.925,91.7 ; v1@31.9,87.475 31.125,86.7 31.125,84.35 32.3,83.175 32.3,81.045 33.149,80.196 37.145,80.196 37.371,79.97 37.371,78.305 37.145,78.079 33.02,78.079 32.3,77.359 32.3,69.125 32.9,68.525 32.9,61.45 33.751,60.599 33.751,55.552 33.225,55.025 33.225,36.5 33.55,36.175 v1(33.55,35.925)
SD_D1: CN1.8 R85.1 U13.99 | length 90.3
  Top Layer w0.127: CN1.8@11.825,89.4 11.825,88.45 13.775,86.5 v1(31.9,86.5) ; v1(11.825,90.775) 11.825,89.55 CN1.8@11.9,89.475 ; v1(34.7,32.35) 35.2,32.85 U13.99@35.2,33.675
  Bottom Layer w0.127: v1(11.825,90.775) R85.1@11.825,91.7 ; v1(31.9,86.5) 31.9,83.934 32.554,83.28 32.554,81.15 33.254,80.45 37.25,80.45 37.625,80.075 37.625,78.2 37.25,77.825 33.125,77.825 32.554,77.254 32.554,69.23 33.154,68.63 33.154,61.555 34.005,60.704 34.005,55.43 33.8,55.225 ; 33.792,55.233 33.525,54.966 33.525,36.975 34.04,36.46 34.04,32.985 v1@34.675,32.35
SD_D2: CN1.1 R81.1 U13.111 | length 90.2
  Top Layer w0.127: CN1.1@19.525,89.4 v1(19.525,90.775) 21.75,90.775 23.95,88.575 26.45,88.575 29.021,91.146 30.225,91.146 30.237,91.134 31.508,91.134 32.05,91.675 39.725,91.675 39.934,91.465 39.934,90.772 40.231,90.475 40.875,90.475 41.4,89.95 v1(41.4,89.9) ; U13.111@41.575,36.55 v1@46.9,36.55
  Bottom Layer w0.127: v1(19.525,90.775) R81.1@19.525,91.675 ; v1@41.425,89.925 v1(41.4,89.9) 41.358,89.858 41.358,81.285 41.875,80.768 41.875,79.6 45.15,76.325 45.15,48.781 43.112,46.742 43.112,46.049 46.925,42.235 v1@46.925,36.6
  Bottom Layer w0.2: R81.1@19.525,91.675 R81.1@19.55,91.7
  other v1: 46.925,36.55
SD_D3: CN1.2 R82.1 U13.112 | length 90
  Top Layer w0.127: CN1.2@18.425,89.4 v1(18.425,90.775) 21.375,93.725 25.35,93.725 27.675,91.4 31.416,91.4 31.945,91.929 39.83,91.929 40.4,91.359 40.4,90.975 v1@40.4,90.95 ; U13.112@41.575,37.05 46,37.05 v1@46.425,37.475
  Bottom Layer w0.127: v1(18.425,90.775) R82.1@18.425,91.675 ; v1(40.425,90.975) 40.429,90.971 40.429,89.662 41.104,88.987 41.104,81.18 41.604,80.68 41.604,79.512 44.896,76.22 44.896,48.886 42.858,46.847 42.858,45.911 46.4,42.368 46.4,37.5 v1@46.4,37.475
  other v1: 46.425,37.5
SD_DETECT: R79.1 U13.49 | length 62
  Top Layer w0.127: v1@13.725,47.075 13.744,47.056 20.325,47.056 U13.49@20.325,47.05 19.35,47.05
  Bottom Layer w0.127: R79.1@10.2,98.2 9.175,97.175 9.175,73.05 7.95,71.825 7.95,64.5 12.1,60.35 12.1,54.675 13.45,53.325 13.45,52.275 13.7,52.025 v1(13.7,47.075)
STLINK_JTCK_SWCLK: R92.2 SB18.2 U13.109 | length 75.4
  Top Layer w0.127: U13.109@41.575,35.55 49.465,35.55 51.125,37.21 53.149,37.21 53.159,37.2 53.775,37.2 55,35.975 65,35.975 v1(66.775,37.75)
  Bottom Layer w0.127: R92.2@58.625,78.7 58.035,78.11 58.035,74.469 57.821,74.255 57.821,70.395 58.67,69.546 61.679,69.546 62.575,68.65 62.575,58.45 63.85,57.175 63.85,51.5 65.175,50.175 65.175,49.8 65.867,49.108 65.867,48.767 65.571,48.471 65.571,38.979 v1@66.8,37.75 ; R92.2@58.775,78.775 58.775,80
STLINK_JTDO-SWO: R91.2 SB17.2 U13.133 | length 61.5
  Top Layer w0.127: U13.133@41.575,47.55 44.8,47.55 46.1,46.25 47.2,46.25 48.146,45.304 57.495,45.304 57.525,45.335 59.385,45.335 60.55,46.5 v1(60.55,46.875) ; v1(57.278,75.054) 61.646,75.054 v1(61.675,75.025)
  Bottom Layer w0.127: v1(57.278,75.054) 57.297,75.054 57.313,75.038 57.313,70.184 58.459,69.038 59.953,69.038 60.518,68.472 60.518,52.282 60.859,51.941 60.859,50.575 ; v1(60.55,46.875) 60.55,50.275 60.85,50.575 ; R91.2@60.575,78.7 R91.2@60.575,78.725 SB17.2@60.575,80.275 ; R91.2@60.775,78.7 61.675,77.8 v1(61.675,75.025)
STLINK_JTMS_SWDIO: R89.2 SB15.2 U13.105 | length 84.3
  Top Layer w0.127: U13.105@38.2,33.675 38.2,32.85 38.35,32.7 38.35,30.05 38.575,29.825 41.175,29.825 41.875,30.525 42.625,30.525 42.954,30.195 48.217,30.195 48.753,30.731 49.633,30.731 49.639,30.725 52.975,30.725 55.7,33.45 59.35,33.45 60.375,34.475 67.75,34.475 ; 67.763,34.462 68.05,34.75 68.05,37.355 v1(68.028,37.377)
  Bottom Layer w0.127: 67.375,80.1 67.375,78.8 R89.2@67.425,78.75 ; R89.2@67.425,78.725 67.7,78.725 68.625,77.8 68.625,71.25 66.45,69.075 66.45,65.625 69.175,62.9 69.175,38.524 v1(68.028,37.377)
STLINK_RX: CN13.2 R15.2 U6.13 | length 32.4
  Top Layer w0.127: v1(54.7,81.725) 54.7,82.4 U6.13@54.75,82.45 ; U6.13@54.825,82.45 56.125,82.45 R15.2@56.15,82.475
  Bottom Layer w0.127: CN13.2@52.175,52.5 52.65,52.975 52.65,75.375 54.15,76.875 54.15,81.175 v1(54.7,81.725)
STLINK_TX: CN13.1 R19.2 U6.12 | length 32.6
  Top Layer w0.127: U6.12@53.325,80.95 53.325,80.125 53.875,79.575 v1(56.325,79.575) R19.2@56.325,78.75
  Bottom Layer w0.127: CN13.1@54.825,52.5 54.825,72.225 54.825,74.425 56.325,75.925 v1(56.325,79.575)
STLK_MCO: C8.2 R7.2 R50.2 | length 68.8
  Top Layer w0.127: R50.2@29.75,57.4 30.725,58.375 30.725,61.95 31.125,62.35 31.728,62.35 31.88,62.198 54.873,62.198 v1@55.85,63.175 ; R7.2@51.275,91.65 51.425,91.8 52.35,91.8 C8.2@52.375,91.825 ; C8.2@52.375,91.875 52.375,92.65 52.575,92.85 54.725,92.85 56,91.575 57.675,91.575 v1@58.375,90.875
  Bottom Layer w0.127: v1@55.825,63.175 55.252,63.748 55.252,72.048 55.252,73.977 57.1,75.825 57.1,82.925 57.4,83.225 57.4,87.375 58.35,88.325 v1(58.35,90.9)
  other v1: 55.85,63.15
STM_JTCK: CN14.2 U6.37 | length 56.7
  Top Layer w0.127: U6.37@46.375,87.95 48.2,87.95 v1(49.7,86.45) ; v1(51.152,69.653) 51.206,69.6 v1(56.925,69.6) ; v1(60.253,51.728) 60.253,51.697 60.3,51.65 65.325,51.65 66.375,50.6 66.375,49.595 CN14.2@67.7,48.27
  Bottom Layer w0.127: v1(49.7,86.45) 49.7,80.341 51.152,78.888 v1(51.152,69.653) ; v1(56.925,69.6) 57.741,68.784 59.166,68.784 60.264,67.685 60.264,51.761 60.275,51.75 v1(60.253,51.728)
STM_JTMS: CN14.4 U6.34 | length 66.3
  Top Layer w0.127: U6.34@48.825,89.45 48.825,88.291 50.431,86.685 52.622,86.685 53.849,87.911 53.849,88.155 55.389,89.696 56.916,89.696 57.718,88.893 57.718,87.063 58.175,86.607 v1(58.175,86.15) ; v1(60.875,45.9) 64.7,45.9 67.41,43.19 CN14.4@67.7,43.19
  Bottom Layer w0.127: 57.913,82.638 58.15,82.875 58.15,86.125 v1(58.175,86.15) ; 57.925,82.625 57.781,82.481 57.781,74.574 57.567,74.36 57.567,70.29 58.565,69.292 60.058,69.292 60.772,68.578 60.772,52.387 61.113,52.046 61.113,46.138 v1(60.875,45.9)
STM_RST: C18.2 R18.1 SB3.2 U6.7 | length 5.7
  Top Layer w0.127: U6.7@50.825,80.95 50.825,79.85 51.3,79.375 52.1,79.375 C18.2@52.575,78.9 ; C18.2@52.675,78.85 R18.1@53.625,78.85 54.725,78.85 54.9,78.675 54.9,78.575 SB3.2@54.85,78.525
T_JTCK: SB18.1 U6.15 U6.26 | length 14
  Top Layer w0.127: v1(52.425,85.625) 52.425,83.875 52.85,83.45 U6.15@54.825,83.45 v1@58.675,83.45 ; U6.26@52.825,89.45 52.825,88.35 v1(52.85,88.325) ; v1(58.65,83.425) v1@58.7,83.375
  Bottom Layer w0.127: v1(52.425,85.625) 52.425,87.9 v1(52.85,88.325) 52.85,88.35 v1@52.825,88.375 ; v1(58.65,83.425) 58.65,83.4 58.675,83.375 58.675,81.75
T_JTMS: R8.1 SB15.1 U6.27 | length 24.7
  Top Layer w0.127: R8.1@52.375,90.85 52.325,90.8 U6.27@52.325,89.45 52.325,88.025 52.515,87.835 53.053,87.835 53.341,88.122 53.341,88.366 55.179,90.204 57.126,90.204 58.25,89.08 58.25,87.25 60.6,84.9 60.6,84.275 61.3,83.575 63.85,83.575 64,83.725 65.825,83.725 v1(65.825,83.7)
  Bottom Layer w0.127: v1(65.825,83.7) 65.825,83.225 67.475,81.575 67.475,81.5
T_NRST: SB16.1 U6.18 | length 13.2
  Top Layer w0.127: U6.18@54.825,84.95 56.625,84.95 58.05,84.95 59.679,83.321 64.779,83.321 v1@65,83.1
  Bottom Layer w0.127: v1(65,83.125) 65.25,83.125 65.625,82.75 SB16.1@65.625,81.375 SB16.1@65.625,81.3
T_SWDIO_IN: R8.2 U6.25 | length 1.5
  Top Layer w0.127: U6.25@53.325,89.45 R8.2@53.325,90.95
T_SWO: SB17.1 U6.31 | length 20.5
  Top Layer w0.127: U6.31@50.325,89.45 50.325,87.612 ; 50.337,87.6 50.325,87.612 ; v1(59.975,84.25) 59.975,85.166 57.996,87.145 57.996,88.975 57.021,89.95 55.284,89.95 53.595,88.26 53.595,88.017 52.517,86.939 50.536,86.939 50.325,87.15 50.325,87.612
  Bottom Layer w0.127: v1(59.975,84.25) 60.575,83.65 SB17.1@60.575,81.375
TAG_NRST: CN11.10 R90.1 | length 4.2
  Bottom Layer w0.127: R90.1@65.625,77.325 65.625,73.2 CN11.10@65.7,73.125
TAG_SWCLK: CN11.4 R92.1 | length 12.9
  Bottom Layer w0.127: R92.1@58.725,77.325 58.725,74.8 58.075,74.15 58.075,70.5 58.775,69.8 61.175,69.8 61.875,70.5 CN11.4@61.875,71.875 ; CN11.4@61.95,71.8 CN11.4@62,71.85
TAG_SWDIO: CN11.2 R89.1 | length 11.5
  Bottom Layer w0.127: CN11.2@64.35,71.825 64.35,71.075 65.3,70.125 66.85,70.125 67.975,71.25 67.975,73.725 67.425,74.275 R89.1@67.425,77.325
TAG_SWO: CN11.6 R91.1 | length 4.2
  Bottom Layer w0.127: R91.1@60.575,77.325 60.575,73.3 CN11.6@60.725,73.15
USB_N: CN17.2 U19.6 | length 2.2
  Bottom Layer w0.155: U19.6@43.45,6.145 43.45,5.475 43.75,5.175 43.75,4.75 43.625,4.625 CN17.2@43.625,4.125
USB_OTG_FS_ID: CN17.4 U13.102 U20.1 | length 44
  Top Layer w0.127: U13.102@36.7,33.675 36.65,33.625 36.65,32.916 35.675,31.941 35.675,28.791 35.2,28.316 35.2,25.272 34.749,24.821 32.705,24.821 32.125,24.241 32.125,20.75 34.9,17.975 39.85,17.975 40.8,17.025 40.8,14.8 41.75,13.85 41.75,11.325 v1(41.35,10.925)
  Bottom Layer w0.127: v1(41.35,10.925) 44.9,10.925 45.325,10.5 45.325,6.413 U20.1@45.863,5.875 ; CN17.4@44.925,4.125 44.925,4.9 45.85,5.825 U20.1@45.85,5.85
USB_OTG_FS_N: U13.103 U19.1 | length 35
  Top Layer w0.155: U13.103@37.2,33.675 37.2,32.922 37.26,32.863 37.26,31.848 36.345,30.934 36.345,25.529 33.825,23.009 33.825,21.617 34.892,20.55 40.611,20.55 42.844,18.317 42.844,15.456 43.76,14.54 43.76,9.184 v2(43.45,8.875)
  Bottom Layer w0.155: U19.1@43.45,7.755 v2(43.45,8.875)
USB_OTG_FS_OVRCR: R65.1 U13.92 | length 59.6
  Top Layer w0.127: U13.92@31.7,33.675 31.7,32.85 31.15,32.3 31.15,30.225 30.221,29.296 30.221,26.27 31.196,25.295 31.196,20.601 34.584,17.213 37.003,17.213 37.796,16.42 37.796,12.57 38.343,12.023 39.093,12.023 39.871,11.245 39.871,7.145 41.07,5.946 45.846,5.946 48,8.1 48,17.975 48.525,18.5 52.3,18.5 53.775,17.025 R65.1@53.775,16.425
USB_OTG_FS_P: U13.104 U19.3 | length 35
  Top Layer w0.155: U13.104@37.7,33.675 37.7,32.922 37.641,32.863 37.641,31.691 36.726,30.776 36.726,25.371 34.206,22.851 34.206,21.775 35.05,20.931 40.769,20.931 43.225,18.475 43.225,15.614 44.141,14.698 44.141,9.184 v2(44.45,8.875)
  Bottom Layer w0.155: U19.3@44.45,7.755 v2(44.45,8.875)
USB_OTG_FS_PWR_EN: R63.1 U13.93 | length 54.4
  Top Layer w0.127: 30.692,29.408 31.404,30.12 31.404,32.025 32.2,32.821 U13.93@32.2,33.675 ; 30.7,29.4 30.475,29.175 30.475,26.375 31.45,25.4 31.45,20.707 34.69,17.467 37.108,17.467 38.05,16.525 38.05,12.675 38.448,12.277 39.198,12.277 40.125,11.35 40.125,7.25 41.175,6.2 45.725,6.2 47.746,8.221 47.746,17.254 v1(47.25,17.75) ; v1(48.925,17.725) 48.925,16.675 R63.1@48.975,16.625
  Bottom Layer w0.127: v1(47.25,17.75) 48.9,17.75 v1(48.925,17.725)
USB_OTG_FS_VBUS: C76.2 CN17.1 R67.1 R69.1 U13.101 U15.1 U21.1 | length 61.5
  Top Layer w0.127: U13.101@36.2,33.675 36.2,32.825 35.421,32.046 35.421,28.896 34.946,28.421 34.946,25.377 34.644,25.075 32.581,25.075 31.871,24.365 31.871,20.645 34.795,17.721 39.745,17.721 40.546,16.92 40.546,14.695 41.496,13.745 41.496,12.021 40.8,11.325 40.8,10.4 v1(41.575,9.625)
  Top Layer w0.3: v1(42.975,3) 47.1,3 50.95,6.85 50.95,11.4 51.65,12.1 U15.1@51.65,13.05 ; U15.1@51.625,13.05 U15.1@51.65,13.05 ; R69.1@52.925,11.6 52.925,12.75 C76.2@52.975,12.8 ; R67.1@52.975,14.15 C76.2@52.975,12.8 ; U15.1@51.65,13.05 52.725,13.05 C76.2@52.975,12.8
  Bottom Layer w0.2: v1(41.575,9.625) 41.85,9.35 U21.1@41.85,6.4 41.85,6.2 42.975,5.075 CN17.1@42.975,4.125
  Bottom Layer w0.3: CN17.1@42.961,3.761 42.975,3.746 v1(42.975,3)
USB_P: CN17.3 U19.4 | length 2.2
  Bottom Layer w0.155: CN17.3@44.275,4.125 44.275,4.6 44.15,4.725 44.15,5.15 44.45,5.45 U19.4@44.45,6.145
USB_RENUMN: R6.2 U6.38 | length 31.3
  Top Layer w0.127: U6.38@46.325,87.45 45.55,87.45 45.35,87.65 45.35,89.675 50.225,94.55 v1(56.45,94.55) ; v1(56.45,92.7) 62.925,92.7 63.425,92.2 v1(63.45,92.225) ; R6.2@61.65,97.05 v1(62.425,97.05)
  Bottom Layer w0.127: v1(56.45,92.7) v1(56.45,94.55) ; v1@62.425,97.075 63.45,96.05 v1(63.45,92.225)
USB_STLK_ID: CN2.4 R3.2 | length 1.8
  Top Layer w0.2: R3.2@56.075,99.175 56.075,99.55 56.49,99.965 CN2.4@56.49,100.85
USB_STLK_N: CN2.2 U5.1 U5.6 U6.32 | length 19.6
  Top Layer w0.155: U6.32@49.75,89.782 49.75,92.35 50.744,93.344 58.192,93.344 58.566,93.717 58.566,94.238 58.825,94.497 U5.6@58.825,95.07 U5.1@58.825,96.68 58.85,96.705 58.85,97.85 58.5,98.2 58.5,98.55 57.79,99.26 CN2.2@57.79,100.85
USB_STLK_P: CN2.3 R4.1 U5.3 U5.4 U6.33 | length 19.5
  Top Layer w0.155: U6.33@49.369,90 49.369,92.508 50.586,93.725 58.034,93.725 58.185,93.875 58.185,94.138 57.825,94.497 U5.4@57.825,95.07 U5.3@57.825,96.68 57.825,97.8 58.119,98.094 58.119,98.392 57.14,99.371 CN2.3@57.14,100.85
